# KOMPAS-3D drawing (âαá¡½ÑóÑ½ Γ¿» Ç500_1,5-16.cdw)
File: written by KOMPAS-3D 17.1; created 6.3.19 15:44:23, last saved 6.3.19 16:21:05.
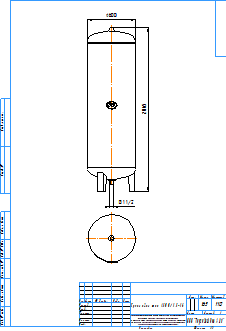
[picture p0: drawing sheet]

Sheet 1: A3, portrait

Title block, sheet 1: name: Гранлевел тип А500/1,5-16; material: Сталь 10  ГОСТ 1050-88; mass: 165; sheets: 1; sheet format: A3; stored path: C:\Users\kka\KOMPAS_Work\!Trash\ГРАНЛЕВЕЛ тип А Расширительный бак\KOMPAS 2D\Гранлевел тип А500_1,5-16.cdw

Views: Вид 1, Проекционный вид 2
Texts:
  kka
  adl
  Рама для чертежей
  Лит-Масса-Масштаб
  Материал-Предприятие
  Масштаб
  Изм.
  Лист
  № докум.
  Подп.
  Дата
  Лит.
  Разраб.
  Пров.
  Т.контр.
  Листов
  Внимание! Данный продукт является объектом авторского права ООО «Торговый Дом АДЛ».
  Запрещается изменение, копирование, распространение
  (в том числе путем копирования на другие сайты и ресурсы в Интернете)
  или любое иное использование информации и объектов без предварительного
  согласия правообладателя (ООО «Торговый Дом АДЛ»).
  Н.контр.
  Утв.
  ООО "Торговый дом АДЛ"
  Изменение
  Номер документа
  Подпись
  Обозначение документа
  Наименование изделия
  Масса изделия по ГОСТ 2.109-73
  Порядковый номер листа
  Общее количество листов в документе
  Характер работы, выполненной лицом, подписавшим документ
  Наименование или индекс предприятия, выпускающего документ
  Инв. № подл.
  Подп. и дата
  Взам. инв. №
  Инв. № дубл.
  Инвентарный номер подлинника по ГОСТ 2.501-68
  Подпись принявшего подлинник в отдел технической документации
  Инвентарный номер подлинника, взамен которого выпущен данный подлинник
  Инвентарный номер дубликата по ГОСТ 2.502-68
  Подпись принявшего дубликат в отдел технической документации
  Справ. №
  Перв. примен.
  Обозначение документа, взамен или на основании которого выпущен данный документ
  Обозначение документа, в котором впервые записан данный документ
  Подпись лица, копировавшего чертеж
  Обозначение формата листа
  !Рама для чертежа
Dimensions and other numbers on the sheet: 2065; 600; 1 1/2; 1:10; 1; 165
